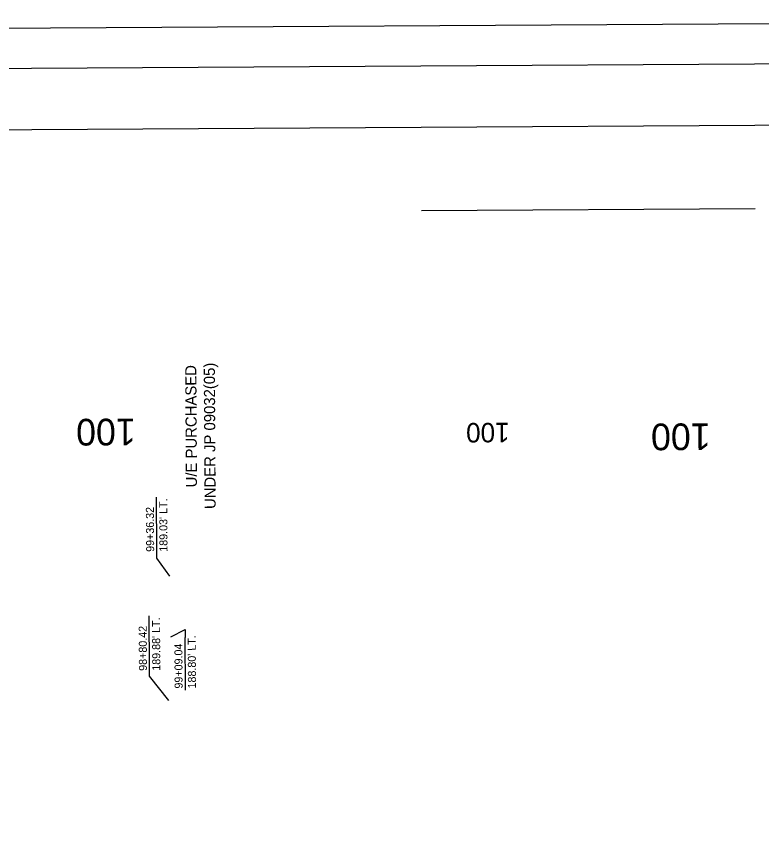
# Model space of a CAD drawing. Extents: x 2150220 to 2151431, y 143266 to 145351.
# Drawn here: x 2150555 to 2150889.7, y 144835.1 to 145205.9 of the extents above; entities that cross this region are included whole.
import ezdxf

# ---------------------------------------------------------------- set-up
doc = ezdxf.new("R2010")
doc.units = 0
for name, color, linetype in [('ALIGN_ROW Line', 7, 'Continuous'), ('EX_Align', 7, 'Continuous'), ('EX_Align_Sta', 7, 'Continuous'), ('PR_Align_Service_B_Sta', 7, 'Continuous'), ('PR_Align_Service_C_Sta', 7, 'Continuous'), ('PR_RW_Txt', 7, 'Continuous'), ('SHT_Plot_Shape_Full', 7, 'Continuous'), ('SHT_Plot_Shape_Half', 7, 'Continuous'), ('SHT_Sheet_Border', 7, 'Continuous')]:
    doc.layers.add(name, color=color, linetype=linetype)

msp = doc.modelspace()

# ---------------------------------------------------------------- linework, layer by layer
at = {"layer": 'ALIGN_ROW Line'}
for p, q in [((2150617.96, 144966.09), (2150617.81, 144989.83)), ((2150614.72, 144913.03), (2150614.58, 144936.51)), ((2150630.86, 144903.18), (2150630.72, 144926.79))]:
    msp.add_line(p, q, dxfattribs=at)
for points in [[(2150623.88, 144954.36), (2150617.98, 144962.49), (2150617.96, 144966.09)], [(2150624.27, 144927.08), (2150630.7, 144930.39), (2150630.72, 144926.79)], [(2150623.37, 144898.46), (2150614.75, 144909.43), (2150614.72, 144913.03)]]:
    msp.add_lwpolyline(points, dxfattribs=at)
at = {"layer": 'EX_Align'}
msp.add_line((2150736.96, 145118.72), (2150886.88, 145119.62), dxfattribs=at)
at = {"layer": 'SHT_Plot_Shape_Full'}
msp.add_lwpolyline([(2150231, 143398.77), (2150220.19, 145198.73), (2151420.16, 145205.94), (2151430.98, 143405.98)], close=True, dxfattribs=at)
at = {"layer": 'SHT_Plot_Shape_Half'}
msp.add_lwpolyline([(2150271.76, 143480.89), (2150261.54, 145180.86), (2151361.52, 145187.47), (2151371.74, 143487.5)], close=True, dxfattribs=at)
at = {"layer": 'SHT_Sheet_Border'}
msp.add_lwpolyline([(2151336.69, 145159.82), (2151346.15, 143584.85), (2150296.17, 143578.54), (2150286.71, 145153.51)], close=True, dxfattribs=at)

# ---------------------------------------------------------------- texts
at = {"layer": 'ALIGN_ROW Line'}
for s, p in [("189.03' LT.", (2150622.82, 144965.34)), ('99+36.32', (2150616.82, 144965.3)), ("189.88' LT.", (2150619.59, 144911.86)), ('98+80.42', (2150613.59, 144911.82)), ("188.80' LT.", (2150635.62, 144903.88)), ('99+09.04', (2150629.62, 144903.84))]:
    msp.add_text(s, height=3.6, rotation=90.3441, dxfattribs=at).set_placement(p)
at = {"layer": 'EX_Align_Sta'}
msp.add_text('100', height=8.75, rotation=180.3443, dxfattribs=at).set_placement((2150776.5, 145023.33))
at = {"layer": 'PR_Align_Service_B_Sta'}
msp.add_text('100', height=12, rotation=180.3443, dxfattribs=at).set_placement((2150866.82, 145023.11))
at = {"layer": 'PR_Align_Service_C_Sta'}
msp.add_text('100', height=12, rotation=180.3443, dxfattribs=at).set_placement((2150608.49, 145025.23))
at = {"layer": 'PR_RW_Txt'}
for s, p in [('U/E PURCHASED', (2150636.08, 144994.28)), ('UNDER JP 09032(05)', (2150644.48, 144984.56))]:
    msp.add_text(s, height=5, rotation=90.3242, dxfattribs=at).set_placement(p)

doc.saveas('drawing.dxf')
